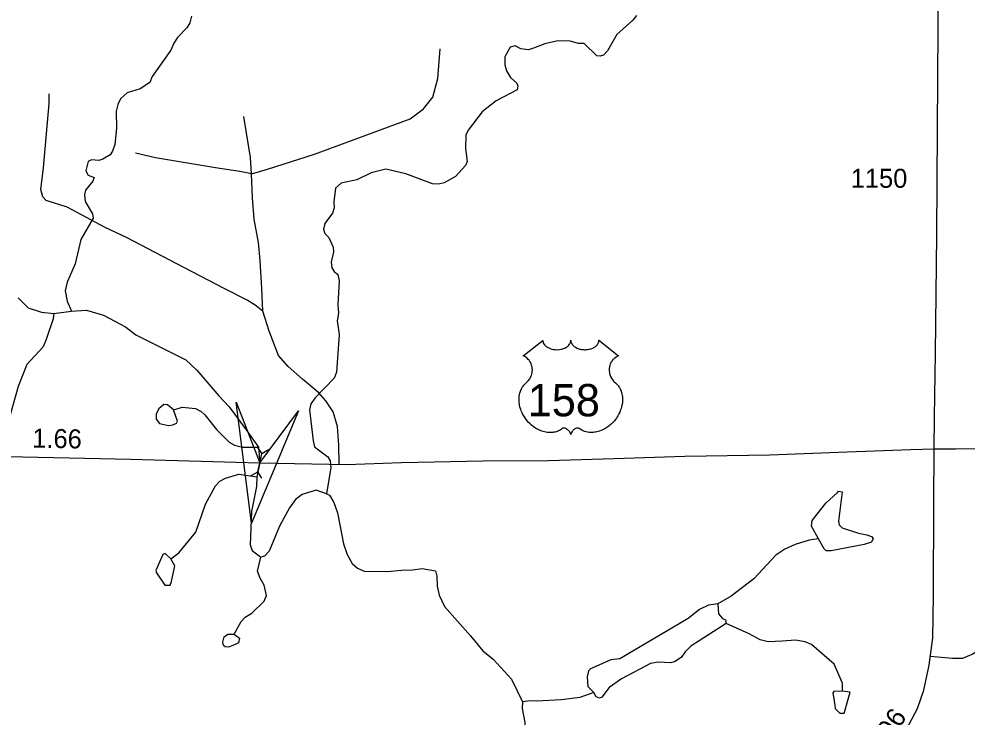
# Model space of a CAD drawing. Extents: x 2056842 to 2160602, y 826753 to 1016856.
# Drawn here: x 2080603 to 2086830, y 931304 to 935892 of the extents above; entities that cross this region are included whole.
import ezdxf

# ---------------------------------------------------------------- set-up
doc = ezdxf.new("R2010")
doc.units = 0
for name, color, linetype in [('Exist Hydrographic Creek Single Shore', 7, 'Continuous'), ('Exist Hydrographic Misc Water Feature', 7, 'Continuous'), ('Exist Hydrographic Pond Under 1500 Sq Ft', 7, 'Continuous'), ('Exist Road Non-System Type 51', 7, 'Continuous'), ('Exist Road Primary US Attributed', 7, 'Continuous'), ('Exist Road Primary US Mileage Hundredths English Label', 7, 'Continuous'), ('Exist Road Primary US Shield CELL', 7, 'Continuous'), ('Exist Road Primary US Shield Number Label', 7, 'Continuous'), ('Exist Road Secondary Mileage Hundredths English Label', 7, 'Continuous'), ('Exist Road Secondary Structure Culvert Attributed CELL', 7, 'Continuous'), ('Exist Road Secondary Structure Culvert CELL', 7, 'Continuous'), ('Exist Road Secondary Type 51 Attributed', 7, 'Continuous'), ('Exist Road Secondary Type 51 Number Label', 7, 'Continuous')]:
    doc.layers.add(name, color=color, linetype=linetype)

msp = doc.modelspace()

# ---------------------------------------------------------------- linework, layer by layer
at = {"layer": 'Exist Hydrographic Creek Single Shore'}
for points in [[(2081736.9, 935909.8), (2081725, 935865.8), (2081705.2, 935833.7), (2081643.4, 935769.5), (2081619.6, 935733.4), (2081599.8, 935685.4), (2081478.2, 935513), (2081462.4, 935475), (2081398.4, 935432.7), (2081314.5, 935406.5), (2081270.6, 935366.4), (2081252.8, 935330.3), (2081240.9, 935286.3), (2081243.4, 935174.3), (2081233.5, 935066.3), (2081217.7, 935022.2), (2081201.8, 934998.1), (2081154, 934970), (2081127.9, 934961.9), (2081080, 934965.8), (2081058, 934953.7), (2081042.2, 934893.7), (2081056.4, 934865.8), (2081096.4, 934849.9), (2081088.4, 934825.9), (2081040.6, 934765.7), (2081032.8, 934737.7), (2081036.9, 934691.7), (2081085.1, 934609.9), (2081091.2, 934581.9), (2081009.6, 934441.6), (2080972.1, 934281.5), (2080920.4, 934161.3), (2080906.7, 934105.3), (2080918.8, 934037.4), (2080947.1, 933971.4)], [(2084658.6, 935914.8), (2084634.6, 935882.8), (2084530.9, 935788.5), (2084469.3, 935682.1), (2084441.5, 935654.1), (2084421.3, 935646), (2084397.5, 935650.1), (2084315.1, 935729.6), (2084277.1, 935729.7), (2084223.2, 935745.3), (2084141.3, 935747.3), (2084057.2, 935727.1), (2083981.4, 935698.8), (2083949.4, 935688.6), (2083899.3, 935694.6), (2083861.3, 935714.4), (2083829.3, 935706.2), (2083793.5, 935642), (2083793.8, 935590.1), (2083805.8, 935550.2), (2083831.7, 935506.3), (2083872, 935470.4), (2083880.1, 935450.5), (2083876, 935426.3), (2083736.4, 935354.1), (2083644.6, 935281.5), (2083552.9, 935161.3), (2083537.1, 935127.2), (2083535.3, 935039.3), (2083547.6, 934955.4), (2083535.6, 934927.4), (2083469.8, 934857.2), (2083396.1, 934814.8), (2083358.2, 934806.7), (2083318.2, 934808.5), (2083144, 934874.2), (2083011.7, 934903.8), (2082916.1, 934879.6), (2082821.9, 934835.2), (2082718.1, 934812.8), (2082682.3, 934778.7), (2082670.6, 934690.7), (2082672.8, 934650.6), (2082662.8, 934614.8), (2082610.9, 934546.6), (2082603.2, 934510.3), (2082611.2, 934482.6), (2082639.2, 934454.5), (2082667.4, 934392.5), (2082669.7, 934360.6), (2082653.8, 934292.7), (2082658, 934256.5), (2082673.9, 934232.6), (2082698.1, 934212.7), (2082706.1, 934170.9), (2082696.6, 934014.9), (2082700.7, 933958.7), (2082693.1, 933906.7), (2082705.4, 933818.8), (2082688.1, 933570.8), (2082672.2, 933530.7), (2082548.4, 933402.4), (2082520.7, 933362.3), (2082511, 933322.1), (2082535.3, 933118.2), (2082543.7, 933080.2), (2082631.9, 933014.8), (2082647.7, 932986.5), (2082652.1, 932942.8), (2082622.6, 932770.5)], [(2080598.5, 934058.1), (2080662.8, 933992.4), (2080750.8, 933964.7), (2080831, 933956.8)], [(2080831, 933956.8), (2080946.8, 933971.4)], [(2080946.8, 933971.4), (2081047, 933977.6), (2081158.9, 933944.1), (2081303.3, 933868.6), (2081371.5, 933816.6), (2081699.8, 933651.6), (2081772.2, 933583.9), (2081914.7, 933414.2), (2081982.8, 933342.6), (2082095.1, 933190.9), (2082175.2, 933077.2)], [(2080831, 933957.1), (2080827.1, 933921), (2080781.8, 933784.9), (2080761.9, 933736.9), (2080654.3, 933620.5), (2080598.5, 933476.3), (2080523.4, 933210.2), (2080481.6, 933126), (2080424, 933069.8)], [(2082175.2, 933077.2), (2082184.7, 932974.9), (2082164.5, 932883.3)], [(2082164.5, 932883.3), (2082163.1, 932818.6), (2082131, 932655), (2082121.8, 932435), (2082133.8, 932399), (2082192, 932355.1)], [(2082622.6, 932770.5), (2082554.5, 932794.2), (2082462.7, 932765.9), (2082418.7, 932734), (2082378.8, 932677.8), (2082313.3, 932557.7), (2082245.6, 932393.4), (2082215.7, 932361.2), (2082192, 932355.1)], [(2082622.6, 932770.5), (2082642.4, 932762.5), (2082670.6, 932714.7), (2082694.8, 932645), (2082733.6, 932443), (2082757.7, 932372.9), (2082791.9, 932313.2), (2082826, 932281.3), (2082870.3, 932261.3), (2083022.1, 932259.8), (2083116.2, 932270), (2083188.1, 932270.5), (2083251.9, 932280.7), (2083337.9, 932264.8), (2083348.3, 932228.8), (2083350.3, 932164.8), (2083362.5, 932105.1), (2083398.7, 932029.2), (2083569.2, 931837.7), (2083649.9, 931737.9), (2083718, 931684), (2083838.3, 931552.5), (2083910.7, 931402.7)], [(2083910.7, 931402.7), (2083908.8, 931358.8), (2083925.2, 931266.9), (2083907.7, 931054.6), (2083832.6, 930770.4)]]:
    msp.add_lwpolyline(points, dxfattribs=at)
at = {"layer": 'Exist Hydrographic Misc Water Feature'}
for points in [[(2081619, 933323.6), (2081675, 933339.8), (2081763, 933332.1), (2081799.1, 933312.2), (2081823.3, 933290.3), (2081901.4, 933194.5), (2081982.7, 933109.6), (2082019.1, 933089.4), (2082071.6, 933077.2), (2082175.2, 933077.2)], [(2081600.2, 932343.6), (2081652, 932383.7), (2081765.6, 932518.1), (2081827, 932702.3), (2081894.6, 932822.4), (2081922.5, 932854.5), (2081958.4, 932872.7), (2082046.4, 932898.9), (2082164.5, 932883.3)], [(2085853.4, 932474.9), (2085809.3, 932558.7), (2085813.2, 932594.8), (2085902.8, 932709), (2085978.4, 932779.3)], [(2085978.4, 932779.3), (2085986.4, 932787.3), (2086010.4, 932783.4), (2085985, 932591.2), (2085989.1, 932567.3), (2086009.2, 932547.3), (2086117.3, 932511.7), (2086171.4, 932501.9), (2086203.4, 932489.9), (2086213.2, 932478), (2086203.4, 932453.9), (2086155.4, 932437.8)], [(2085853.4, 932474.9), (2085793.5, 932466.7), (2085701.6, 932438.4), (2085633.5, 932406.2), (2085573.7, 932368), (2085430.1, 932211.6), (2085280.6, 932099.1), (2085192.9, 932046.8)], [(2086155.4, 932437.8), (2085937.6, 932395.1), (2085905.6, 932395.1), (2085891.5, 932409), (2085853.4, 932474.9)], [(2082015.6, 931848.9), (2082061.3, 931931.1), (2082089.4, 931959.2), (2082133.3, 931987.2), (2082212.9, 932065.6), (2082228.9, 932101.6), (2082214.5, 932169.5), (2082186.4, 932215.4), (2082170.4, 932263.4), (2082192.2, 932355.4)], [(2085192.9, 932046.8), (2085132.8, 932038.7), (2085072.9, 932010.5), (2084999.1, 931952.3), (2084550, 931686.8), (2084490, 931678.6), (2084356.3, 931620.2), (2084344.2, 931608.2), (2084334.3, 931568.2), (2084338.6, 931504.1), (2084378.6, 931464.4)], [(2085192.9, 932046.8), (2085197, 931982.8), (2085223, 931951), (2085243.1, 931943), (2085247.2, 931919)], [(2085247.2, 931919), (2085015.7, 931770.3), (2084977.8, 931732.2), (2084954, 931696.1), (2084912, 931668), (2084884.1, 931660), (2084801.9, 931663.6), (2084752, 931655.5), (2084560.3, 931554.9), (2084478.5, 931498.6), (2084430.7, 931434.5), (2084414.9, 931428.4), (2084394.6, 931436.4), (2084378.6, 931464.4)], [(2086012.5, 931473.5), (2086012.3, 931525.5), (2085957.9, 931651.3), (2085807.6, 931780.8), (2085767.6, 931798.6), (2085703.5, 931808.4), (2085615.5, 931802.2), (2085523.6, 931797.9), (2085471.3, 931811.7), (2085399.4, 931851.5), (2085247.2, 931919)], [(2084378.6, 931464.4), (2084286.8, 931432.1), (2084166.8, 931415.7), (2084002.8, 931407.2), (2083962.8, 931411.1), (2083910.9, 931402.8)]]:
    msp.add_lwpolyline(points, dxfattribs=at)
at = {"layer": 'Exist Hydrographic Pond Under 1500 Sq Ft'}
for points in [[(2081618.8, 933323.5), (2081578.8, 933355.2), (2081554.9, 933357.4), (2081520.8, 933329.2), (2081503.1, 933297.1)], [(2081503.1, 933297.1), (2081503, 933261), (2081525.1, 933233.3), (2081585.2, 933219.2)], [(2081585.2, 933219.2), (2081613.1, 933223.3), (2081637, 933235.6), (2081643.2, 933247.6), (2081618.8, 933323.5)], [(2081599.8, 932343.5), (2081563.8, 932379.3), (2081547.9, 932371.1), (2081510, 932287.2)], [(2081604.3, 932195.4), (2081626.1, 932297.6), (2081599.8, 932343.5)], [(2081510, 932287.2), (2081502.1, 932267.1), (2081506.3, 932251.2), (2081560.5, 932171.4), (2081596.6, 932171.3), (2081604.3, 932195.4)], [(2081941.5, 931796.6), (2081951.4, 931830.5), (2081975.4, 931848.7), (2082015.5, 931848.9)], [(2082015.5, 931848.9), (2082051.7, 931822.9), (2082043.8, 931790.9), (2082023.6, 931780.8)], [(2082023.6, 931780.8), (2081979.9, 931762.7), (2081957.6, 931764.4), (2081945.7, 931774.5), (2081941.5, 931796.6)], [(2086012.5, 931473.3), (2085954.3, 931471.2), (2085948.3, 931463.1), (2085960.7, 931381.2)], [(2086030.6, 931351.5), (2086062.2, 931467.3), (2086012.5, 931473.3)], [(2085960.7, 931381.2), (2085964.8, 931359.1), (2085994.7, 931329.3), (2086022.9, 931329.3), (2086030.6, 931351.5)]]:
    msp.add_lwpolyline(points, dxfattribs=at)
at = {"layer": 'Exist Road Non-System Type 51'}
for points in [[(2082130.5, 934873.8), (2082235, 934903.7), (2082543.6, 935002.9), (2083171.3, 935235.7), (2083260.8, 935301.3), (2083321.6, 935376.5), (2083353.6, 935501.3), (2083369.5, 935696)], [(2082204, 933972.1), (2082153.7, 934010.5), (2082100.9, 934044.1), (2081950.6, 934120.9), (2081640.4, 934282.5), (2081308.8, 934454.6), (2081168, 934520.2), (2080984.1, 934619.4), (2080918.6, 934654.6), (2080781.1, 934699.4), (2080758.7, 934723.4), (2080747.5, 934769.8), (2080763.4, 934912.9), (2080800.2, 935335.3), (2080801.8, 935399.3)], [(2082130.5, 934873.8), (2082123.1, 934982.1), (2082079.9, 935250.9)], [(2082130.5, 934873.8), (2082052.7, 934889.3), (2081894.4, 934913.3), (2081498.6, 934978.1), (2081369.1, 935008.5)], [(2082204, 933972.1), (2082197.6, 934120.9), (2082188, 934303.4), (2082176.8, 934423.4), (2082148.1, 934576.2), (2082136.9, 934715.4), (2082130.5, 934873.8)], [(2082705.2, 932965.3), (2082703.9, 933090.6), (2082695.9, 933212.3), (2082667.1, 933309.9), (2082619.1, 933381.9), (2082573.2, 933433.9), (2082466.1, 933523.5), (2082371.7, 933608.3), (2082307.8, 933680.3), (2082245.4, 933840.4), (2082204, 933972.1)], [(2086588.8, 931704.8), (2086733.9, 931690.9), (2086802.2, 931690.9), (2086863.3, 931716), (2087096.8, 931863.4), (2087113, 931908.4), (2087121.9, 931973.1), (2087170.4, 932001.8), (2087271.9, 932004.5), (2087545, 931993.7), (2087967.1, 931991.9), (2088180.9, 931979.4)]]:
    msp.add_lwpolyline(points, dxfattribs=at)
at = {"layer": 'Exist Road Primary US Attributed'}
for points in [[(2086615, 933065.8), (2086754.5, 933066.2), (2086968.8, 933067.8), (2087255.8, 933080.6), (2087527.7, 933087), (2087808.3, 933091), (2087982.6, 933108.6), (2088126.5, 933143.8), (2088244.8, 933182.3), (2088420.7, 933254.3), (2088845.3, 933439.1), (2089452.5, 933704.2), (2089891.6, 933889.3), (2090132.3, 933982.4), (2090679.4, 934221.5), (2091273.8, 934469), (2091725.5, 934661), (2092051.7, 934805), (2092677.7, 935064.9), (2093273.6, 935314.1), (2093861.1, 935518.5), (2094214.5, 935609.7), (2094739.8, 935742.3), (2095477.5, 935930.9)], [(2077868.8, 933124.2), (2077988.2, 933095.4), (2078148.1, 933092.2), (2078474.3, 933076.2), (2079442.1, 933050.6), (2080222.4, 933021.8), (2081336.5, 932999.4), (2082184.7, 932974.9), (2082754.6, 932964.3), (2083116, 932977.1), (2083650, 932986.7), (2084081, 932989.1), (2084512.7, 933001.9), (2084975.7, 933017.1), (2085535.3, 933026.7), (2086043, 933046.7), (2086460.4, 933061.1), (2086615, 933065.8)]]:
    msp.add_lwpolyline(points, dxfattribs=at)
at = {"layer": 'Exist Road Primary US Shield CELL'}
msp.add_lwpolyline([(2084043.4, 933779.3), (2084043.7, 933773.9), (2084045, 933767.6), (2084046, 933764.4), (2084049, 933758.1), (2084053.8, 933750.8), (2084060.6, 933743.5), (2084068.3, 933737.2), (2084073.5, 933733.9), (2084082.2, 933729.2), (2084092.2, 933725), (2084103.3, 933721.8), (2084114.6, 933719.5), (2084127, 933718.2), (2084139.2, 933717.9), (2084152.4, 933718.9), (2084167, 933721.7), (2084173.7, 933723.5), (2084181.3, 933726.1), (2084188.3, 933729), (2084195.9, 933733.1), (2084202.1, 933737), (2084206.9, 933740.5), (2084213.7, 933747), (2084219.2, 933753.8), (2084221.4, 933757.6), (2084223.4, 933761.2), (2084226.1, 933769), (2084226.9, 933772.4), (2084227.4, 933779.5), (2084227.9, 933773.6), (2084228.5, 933769.8), (2084229.5, 933766.2), (2084231, 933762.3), (2084233.7, 933756.8), (2084236.7, 933752.3), (2084242.5, 933745.5), (2084246, 933742.2), (2084249.3, 933739.5), (2084258, 933733.5), (2084268.3, 933728.3), (2084273.3, 933726.1), (2084278.4, 933724.3), (2084285, 933722.3), (2084291.7, 933720.7), (2084298.4, 933719.6), (2084305.3, 933718.6), (2084312.2, 933718.1), (2084317.9, 933717.9), (2084324.9, 933718), (2084331.4, 933718.4), (2084338, 933719.2), (2084345.3, 933720.4), (2084351.1, 933721.7), (2084358.9, 933723.7), (2084365.9, 933726.2), (2084372, 933728.9), (2084380, 933733.1), (2084386.4, 933737.1), (2084391.2, 933740.9), (2084396.8, 933746.1), (2084402.1, 933752.2), (2084405.2, 933756.7), (2084407.4, 933761.3), (2084409.5, 933766.2), (2084410.7, 933771.4), (2084411.3, 933775.8), (2084411.4, 933779.7), (2084540, 933677.2), (2084537, 933676.1), (2084530, 933672.6), (2084524.5, 933669.4), (2084515.6, 933663.1), (2084511.8, 933659.7), (2084508, 933656.2), (2084504.5, 933652.4), (2084501.5, 933648.8), (2084497.7, 933643.6), (2084494.4, 933638.5), (2084491.1, 933632.8), (2084488.7, 933627.8), (2084484.8, 933617.5), (2084482.9, 933610.9), (2084481.7, 933605.4), (2084480.2, 933593.9), (2084479.8, 933588.5), (2084479.8, 933583.1), (2084480.1, 933577.4), (2084480.6, 933571.9), (2084481.6, 933566.2), (2084482.5, 933561.2), (2084484.1, 933555), (2084486.4, 933547.9), (2084489.2, 933541), (2084495.1, 933529.8), (2084502.6, 933518.4), (2084508, 933512), (2084513.3, 933506.5), (2084521.3, 933499.9), (2084525.6, 933496.1), (2084530.5, 933491.1), (2084538.6, 933481.8), (2084541.8, 933477.4), (2084545.1, 933472.4), (2084548.2, 933467.3), (2084551.2, 933461.9), (2084553.6, 933457.1), (2084558.2, 933446.1), (2084561.5, 933435.3), (2084563, 933429.7), (2084565.4, 933417.1), (2084566.3, 933410.9), (2084567.3, 933398.6), (2084567.3, 933383.7), (2084566.2, 933369.5), (2084563.5, 933353), (2084561.3, 933343.2), (2084557.9, 933331.7), (2084554.7, 933321.7), (2084548.8, 933307.1), (2084543.6, 933296.4), (2084536.8, 933284), (2084532.2, 933276.5), (2084526.8, 933268.4), (2084520, 933259.1), (2084512.1, 933249.2), (2084502.6, 933238.8), (2084495, 933231.2), (2084484.9, 933222.2), (2084478.9, 933217.2), (2084470.2, 933210.6), (2084458.4, 933202.7), (2084446.7, 933196), (2084436.7, 933190.9), (2084427.9, 933187.1), (2084416.5, 933182.8), (2084397.5, 933177.5), (2084390.6, 933176.1), (2084382.4, 933174.9), (2084374.7, 933174.1), (2084367.3, 933173.6), (2084357.3, 933173.6), (2084347.3, 933174.4), (2084337.9, 933175.8), (2084328.1, 933177.8), (2084317.9, 933180.9), (2084308.6, 933184.5), (2084299.1, 933189.1), (2084283.2, 933199.2), (2084278.6, 933201.6), (2084276, 933202.3), (2084269.9, 933202.6), (2084264.1, 933201.4), (2084258.2, 933199), (2084254.6, 933197.1), (2084249.9, 933194), (2084246.2, 933191.1), (2084241.8, 933186.9), (2084238.8, 933183.4), (2084236.5, 933180.7), (2084232, 933173.6), (2084230.4, 933170.3), (2084228.7, 933166), (2084227.3, 933159.6), (2084225.2, 933167.6), (2084222.9, 933173), (2084220.2, 933177.5), (2084217.3, 933181.5), (2084212.8, 933186.7), (2084208.8, 933190.6), (2084203.9, 933194.5), (2084198.8, 933197.7), (2084194.6, 933199.8), (2084190.8, 933201.2), (2084186.2, 933202.4), (2084182.4, 933202.7), (2084179.3, 933202.6), (2084175, 933201.6), (2084169.2, 933197.4), (2084163.7, 933193.6), (2084157.7, 933189.9), (2084150.5, 933186.1), (2084145.3, 933183.7), (2084139.1, 933181.2), (2084131.8, 933178.8), (2084123.9, 933176.8), (2084115.8, 933175.2), (2084108.6, 933174), (2084101, 933173.3), (2084094, 933173.1), (2084086.8, 933173.2), (2084080.1, 933173.7), (2084072.2, 933174.4), (2084062.5, 933175.8), (2084054.5, 933177.7), (2084046, 933179.9), (2084037.2, 933182.7), (2084027.9, 933186.3), (2084016.2, 933191.3), (2084008.1, 933195.5), (2083995.2, 933202.9), (2083980.2, 933213.3), (2083968.8, 933222.5), (2083960.5, 933230), (2083948.3, 933242.5), (2083941.1, 933250.6), (2083929.8, 933265.2), (2083922.6, 933275.8), (2083918, 933283.5), (2083911.1, 933296), (2083907.4, 933303.8), (2083902.5, 933315.2), (2083898.7, 933325.6), (2083895.5, 933335.5), (2083893.8, 933341.8), (2083891.3, 933352.8), (2083889.9, 933360.6), (2083888.4, 933371.4), (2083887.6, 933382.7), (2083887.5, 933393.1), (2083887.7, 933401.8), (2083888.7, 933411.9), (2083890.4, 933422.6), (2083892.5, 933431.8), (2083894.3, 933438.4), (2083897.1, 933446.4), (2083900.7, 933455.3), (2083904.9, 933463.8), (2083909, 933470.9), (2083914.1, 933478.5), (2083919.1, 933485), (2083925.7, 933492.1), (2083932.5, 933498.6), (2083938.8, 933503.7), (2083946.2, 933511), (2083950.1, 933515.4), (2083954.8, 933521.6), (2083958.5, 933527.3), (2083961.4, 933532.4), (2083965.4, 933539.9), (2083967.7, 933545.5), (2083970.7, 933554.2), (2083972.2, 933560.3), (2083973.7, 933568.1), (2083974.7, 933575.5), (2083975, 933584.7), (2083974.8, 933592.3), (2083973.8, 933601.1), (2083972.2, 933609.7), (2083970.1, 933617.1), (2083967, 933625.6), (2083964, 933631.8), (2083959.1, 933640.3), (2083953.6, 933648.1), (2083948, 933654.5), (2083942.3, 933660.2), (2083936.8, 933664.4), (2083931.6, 933668.2), (2083925.1, 933672.1), (2083918.8, 933675.2), (2083914.8, 933676.8)], close=True, dxfattribs=at)
at = {"layer": 'Exist Road Secondary Structure Culvert Attributed CELL'}
msp.add_lwpolyline([(2082439.8, 933316.5), (2082131.1, 932578.5), (2082029.4, 933372), (2082184.7, 932974.9)], close=True, dxfattribs=at)
at = {"layer": 'Exist Road Secondary Structure Culvert CELL'}
for p, q in [((2082170.4, 933076.1), (2082198.4, 933033.8)), ((2082170.9, 932916), (2082198.4, 933033.8)), ((2082242.2, 933059.4), (2082198.4, 933033.8)), ((2082127.1, 932890.4), (2082170.9, 932916)), ((2082198.9, 932873.6), (2082170.9, 932916))]:
    msp.add_line(p, q, dxfattribs=at)
at = {"layer": 'Exist Road Secondary Type 51 Attributed'}
for points in [[(2086615, 933065.8), (2086615.5, 933274.5), (2086622.7, 933694.6), (2086631.5, 934473), (2086637.1, 935168.3), (2086639.5, 935831.6), (2086641.1, 936342.9), (2086647.5, 937151), (2086645.1, 937659.1), (2086651.6, 938176.1), (2086654.8, 938582.5), (2086662.4, 938897)], [(2086132.6, 928286.2), (2086054.5, 928454.2), (2085876.7, 928788.4), (2085783.3, 928973.5), (2085744.7, 929089.4), (2085725, 929252.9), (2085714.2, 929400.3), (2085757.3, 929606.9), (2085909, 930127.1), (2085989.8, 930389.4), (2086100.2, 930645.5), (2086215.2, 930862.9), (2086322.9, 931031.8), (2086413.6, 931187.3), (2086505.2, 931359.8), (2086546.5, 931480.2), (2086580.6, 931643.7), (2086604.8, 931824.3), (2086610.2, 932102.8), (2086612.9, 932709.2), (2086615, 933065.8)]]:
    msp.add_lwpolyline(points, dxfattribs=at)

# ---------------------------------------------------------------- texts
at = {"layer": 'Exist Road Primary US Mileage Hundredths English Label'}
msp.add_text('1.66', height=125, rotation=358.84946, dxfattribs=at).set_placement((2080689.3, 933075))
at = {"layer": 'Exist Road Primary US Shield Number Label'}
msp.add_text('158', height=212.5, dxfattribs=at).set_placement((2083944.6, 933280))
at = {"layer": 'Exist Road Secondary Mileage Hundredths English Label'}
msp.add_text('.96', height=125, rotation=55.7509, dxfattribs=at).set_placement((2086307.7, 931112.7))
at = {"layer": 'Exist Road Secondary Type 51 Number Label'}
msp.add_text('1150', height=125, dxfattribs=at).set_placement((2086066.2, 934781.9))

doc.saveas('drawing.dxf')
